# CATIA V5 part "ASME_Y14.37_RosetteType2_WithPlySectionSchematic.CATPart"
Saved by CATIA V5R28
Part number: 333X3333-303
Revision: --
Nomenclature: ASME_Y14.37_RosetteType2
Bounding box of the stored display mesh (mm): x -124.246 to 158.032, y -397.046 to -361.72, z 2.54 to 106.879
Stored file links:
  C:\Users\jvl2147\Documents\ASME Y14.37\PartExamples\ASME_Y14.37_RosetteType2_WithPlySectionSchematic.CATPart
  \\NW\Data\MSE-Composites\ASME Y14.37\ASME Y-14.37_COMPOSITES.CATMaterial
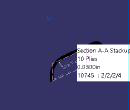
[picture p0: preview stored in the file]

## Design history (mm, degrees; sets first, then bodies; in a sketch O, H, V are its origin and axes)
AxisSystem1 "ROSETTE COORDINATE SYSTEM": origin (-72.9205, -637.9645, 93.98), X (0.5026, 0.8645, 0), Y (-0.8645, 0.5026, 0), Z (0, 0, 1)
CompParametersFeature1 "CATCoParametersFeatName": Value 0, Value 45, Value -45, Value 90
CompEOPGroupFeature1 "CATCoEOPGroupFeatName"
CompStacking1 "Stacking"
CompIsoThickAreasGroup1 "CATCoIsoThickAreasGroupFeatName": RefAddThickness 0
TTRSSet1
f4a2d38f3ddc11d3a929006094b99c4b_11 "CATTPSSet"
CompReviewTools1 "Review tools"
Set1 "CONSTRUCTION GEOMETRY"
  Set2 "CONSTRUCTION - LAMINATE REFERENCE SURFACE"
    Sketch1 on xy-plane, origin (0, 0, 0), H (1, 0, 0), V (0, 1, 0)
      spline S1 through (-79.505, -649.09) (21.2912, -260.3998) (-51.6257, 228.8061) (37.963, 602.845)
    Plane1: type Normal, Curve Sketch1, RefPoint vertex of Sketch1, Ratio 0
    Sketch2 on Plane1, origin (-464.3095, -417.3341, 0), H (-0.8566, 0.5159, 0), V (0, 0, 1)
      line L1 (-525.4052, 91.6386) -> (-373.0052, 91.6386)
      line L2 (-322.2052, 40.8386) -> (-322.2052, 0)
      line L3 (-576.2052, 0) -> (-576.2052, 40.8386)
      reference projected point E1 (-449.2052, 0) from vertex of Sketch1
      reference projected point E2 (-449.2052, 0) from vertex of Sketch1
      arc A1 centre (-373.0052, 40.8386) radius 50.8 from (-373.0052, 91.6386) to (-322.2052, 40.8386) cw
      arc A2 centre (-525.4052, 40.8386) radius 50.8 from (-576.2052, 40.8386) to (-525.4052, 91.6386) cw
      distance E1 L2 = 127
      distance E2 L3 = 127
      radius A1 = 50.8
      radius A2 = 50.8
      horizontal: L1 H
      vertical: L2 V, L3 V
      tangency: A1 L1, A1 L2, A2 L3, A2 L1
    Sweep1: type Unspec, Profile Sketch2, Guide Sketch1
  Set3 "CONSTRUCTION - PLIES EOPS"
    Plane2: type Normal, Curve Sketch1, RefPoint vertex of Sketch1, Ratio 0
    Plane3: type Normal, Curve Sketch1, RefPoint {point type OnCurve, Support Sketch1, Length 1118.262}, Ratio 0.99
    Plane4: type Normal, Curve Sketch1, Ratio 0.01
    Intersect1: ToIntersect1 Plane3, ToIntersect2 Sweep1
    Intersect2: ToIntersect1 Sweep1, ToIntersect2 Plane4
    Plane5: type Offset, RefPlane xy-plane, Offset 2.54
    Intersect3: ToIntersect1 Plane5, ToIntersect2 Join1
    Near1: MultiElement Intersect3, ReferenceElement edge of Sweep1
    Near2: MultiElement Intersect3, ReferenceElement edge of Sweep1
  Set4 "CONSTRUCTION - ROSETTE COORDINATE SYSTEM"
    Intersect4: ToIntersect1 Plane4, ToIntersect2 Project2
    Line1: type Tangency, RefPoint Intersect4, Curve Project2, Start 0, End 25.4
    Plane6: type Offset, RefPlane xy-plane, Offset 93.98
    Project1 "PROJECT": ToProject Sketch1, Support Join1, Direction xy-plane
  Set5 "CONSTRUCTION - ROSETTE TRANSFORMS"
    Line2 "Ply.1_Rosette_transfer_X": type Tangency, RefPoint {point type OnCurve, Support Project2, Length 288.56}, Curve Project2, Support Join1, Start 0, End 25.4
    Line3 "Ply.1_Rosette_transfer_X.Renamed": type Tangency, RefPoint {point type OnCurve, Support Project2, Length 536.186}, Curve Project2, Support Join1, Start 25.4, End 0
    Line4 "Ply.1_Rosette_transfer_X.Renamed": type Tangency, RefPoint {point type OnCurve, Support Project2, Length 783.62}, Curve Project2, Support Join1, Start 25.4, End 0
    Line5 "Ply.1_Rosette_transfer_X.Renamed": type Tangency, RefPoint {point type OnCurve, Support Project2, Length 1274.71}, Curve Project2, Support Join1, Start 25.4, End 0
    Line6 "Ply.1_Rosette_transfer_X.Renamed": type Tangency, RefPoint {point type OnCurve, Support Project2, Length 1017.245}, Curve Project2, Support Join1, Start 25.4, End 0
    AxisSystem2 "ROSETTE COORDINATE SYSTEM": origin (16.8931, -379.3831, 93.98), X (0.1242, 0.9923, 0), Y (-0.9923, 0.1242, 0), Z (0, 0, 1)
    AxisSystem3 "ROSETTE COORDINATE SYSTEM.Renamed": origin (7.1166, -132.8437, 93.98), X (-0.1632, 0.9866, 0), Y (-0.9866, -0.1632, 0), Z (0, 0, 1)
    AxisSystem4 "ROSETTE COORDINATE SYSTEM.Renamed1": origin (-38.9217, 110.2518, 93.98), X (-0.1571, 0.9876, 0), Y (-0.9876, -0.1571, 0), Z (0, 0, 1)
    AxisSystem5 "ROSETTE COORDINATE SYSTEM.Renamed2": origin (29.3229, 586.9432, 93.98), X (0.4677, 0.8839, 0), Y (-0.8839, 0.4677, 0), Z (0, 0, 1)
    AxisSystem6 "ROSETTE COORDINATE SYSTEM.Renamed3": origin (-47.995, 342.9553, 93.98), X (0.1137, 0.9935, 0), Y (-0.9935, 0.1137, 0), Z (0, 0, 1)
    Point1: type OnSurface, Support Join1, Length 362.156, Direction (-0.4364, -0.3881, 0.8118)
    Line7: type Normal, RefPoint Point1, RefSkin Join1, Start 254, End 0
  Plane7 "Section A-A Plane": type Offset, RefPlane YZ plane of AxisSystem2, Offset 0
  Intersect5: ToIntersect1 Project1, ToIntersect2 Plane7
  Intersect6: ToIntersect1 Plane7, ToIntersect2 Join1
  Point2: type OnCurve, Support Intersect6, Ratio 0.25
Set6 "ENGINEERING GEOMETRY"
  Set7 "LAMINATE REFERENCE SURFACE"
    Join1 "LAMINATE REFERENCE SURFACE": Elements Sweep1
  Set8 "GUIDE CURVE - ZERO DEGREE ORIENTATION"
    Project2 "GUIDE CURVE - 0°": ToProject Sketch1, Support Plane6
  Plane8 "Flatten Plane": type Offset, RefPlane XY plane of AxisSystem1, Offset 50.8
Body1 (main body)
Body2 "-303"
  CompIsoThickAreasSolid1 "Area Solid.1": IsoAreasGroup CompIsoThickAreasGroup1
